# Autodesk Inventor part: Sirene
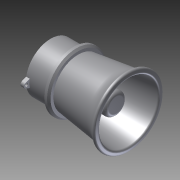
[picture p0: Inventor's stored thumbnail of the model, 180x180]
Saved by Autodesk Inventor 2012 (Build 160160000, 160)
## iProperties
Created: 2012-12
Part Number: Sirene
Material: Default
Document SubType Name: Modeling
Designer: camilla
Density: 1 g/cm^3
Author: camilla
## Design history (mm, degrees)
sketch "Sketch1"
  geometry: L1 (0, 70)-(0, -70); L2 (0, 70)-(65.346, 70); L3 (65.346, 70)-(65.346, 83.064); L4 (65.346, 83.064)-(77.835, 83.064); L5 (77.835, 83.064)-(77.835, 70); L6 (224, 84)-(77.835, 64.958); L7 (77.835, 64.958)-(77.835, 30.341); L8 (77.835, 30.341)-(185.75, 30.341); L9 (185.75, 30.341)-(185.75, 0); L10 (0, 0)-(185.75, 0); L11 (77.835, 70)-(197.65, 85.609); L12 (224, 84)-(220.375, 101.59); L13 (220.375, 101.59)-(197.65, 85.609); 2 further points
  constraints: 26 end point, 6 parallel, 3 perpendicular, 2 coincident, 2 horizontal alignment, 2 midpoint, 1 vertical, 1 vertical alignment
  dimensions: "d0" = 140 distance of L1.start L1.end; "d4" = 84 vertical distance of L9.end L6.start
revolve "Revolution1" sketch "Sketch1" stored, may be unused: angle "d5" = 90 deg
fillet "Fillet1" dims "d6" = 5
fillet "Fillet2" dims "d7" = 10
chamfer "Chamfer1" distance "d8" = 5; stored, may be unused: second distance "d9" = 2, angle "d10" = 45 deg
sketch "Sketch2"
  geometry: L1 (0, 78)-(0, -78); L2 (-4.528, 0)-(4.528, 0); L3 (-11.349, -69.074)-(-7.024, -80.629); L4 (11.349, -69.074)-(7.024, -80.629); L5 (-11.349, 69.074)-(-7.024, 80.629); L6 (11.349, 69.074)-(7.024, 80.629); C1 r 4 at (0, 78); C2 r 4 at (0, -78); A1 r 70 centre (0, 0) between (-11.349, 69.074) and (11.349, 69.074) reference; A2 r 7.5 centre (0, 78) between (7.024, 80.629) and (-7.024, 80.629); A3 r 7.5 centre (0, -78) between (-7.024, -80.629) and (7.024, -80.629); 3 further points
  constraints: 12 end point, 8 point on circle, 8 symmetric about line, 7 coincident, 4 centre point, 2 midpoint, 1 perpendicular, 1 tangent, 1 vertical, 2 other
  dimensions: "d11" = 156 distance of L1.start L1.end; "d12" = 8 diameter of C1; "d13" = 15 diameter of A2
extrude "Extrusion1" join sketch "Sketch2" distance "d14" = 10; taper "d15" = 0 deg
fillet "Fillet3" dims "d16" = 50
fillet "Fillet4" dims "d17" = 5
fillet "Fillet5" dims "d18" = 10
body "Solid1"
